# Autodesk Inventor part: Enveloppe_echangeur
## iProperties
Shininess: 64.0
Length Units: 11269
Angle Units: 11279
Time Units: 11290
Mass Units: 11283
Length Display Precision: 3
Angle Display Precision: 2
Compacted: True
Part Number: Enveloppe_echangeur
Document SubType Name: Modeling
Created: 2008-02
Material: Acier inoxydable, austénitique
Designer: Pascal
Density: 0.0
Volumn: 0.0
Area: 0.0
PropertySet Name: Model Information
Control State: 0
Master: False
Checked Out: False
MATIERE_PIECE: X2CrNi 18-11
OBSERVATIONS: Øext 698,5 ep 3,17
DESIGNATION: Enveloppe echangeur
Author: Pascal
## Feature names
1. Extrusion1
2. Extrusion2
3. Extrusion3
4. Extrusion4
5. Extrusion5
6. Extrusion6
7. Extrusion7
8. Extrusion8
9. Extrusion9
